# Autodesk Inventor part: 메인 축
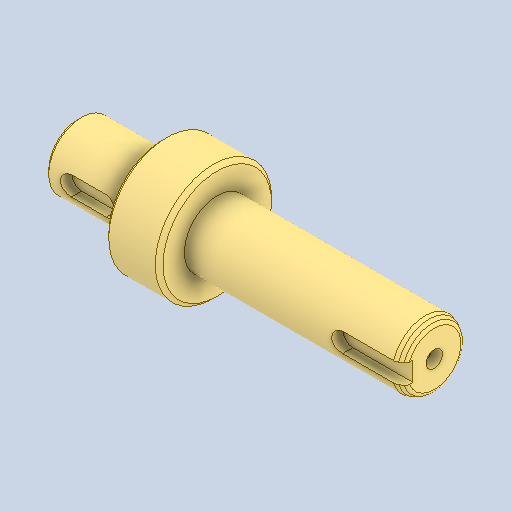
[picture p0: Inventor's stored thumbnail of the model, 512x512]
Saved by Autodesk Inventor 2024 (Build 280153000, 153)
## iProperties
Created: 2026-07
Part Number: 메인 축
Material: 강철, 탄소
Document SubType Name: Modeling
Designer: com
Density: 7.85 g/cm^3
Appearance: 기본값
Author: jhkim
Revision Number: 1
Sending System: Autodesk Inventor 2027
Preprocessor: ST-DEVELOPER v20.1
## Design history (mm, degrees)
node "메인 축1"
node "솔리드2"
node "솔리드1"
